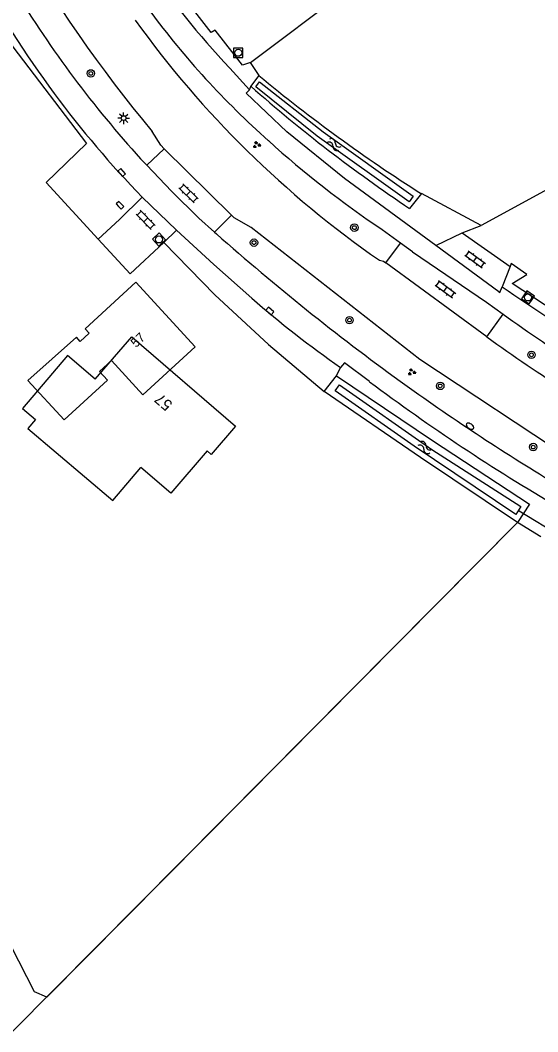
# Model space of a CAD drawing. Extents: x 134297 to 137000, y 403500 to 406000.
# Drawn here: x 136340 to 136395.5, y 404123.8 to 404232.2 of the extents above; entities that cross this region are included whole.
import ezdxf

# ---------------------------------------------------------------- set-up
doc = ezdxf.new("R2010")
doc.units = 0
for name, color, linetype in [('gg-afsc-lijn draadraster', 7, 'Continuous'), ('gg-anno-huisnummerreeks BGT', 7, 'Continuous'), ('gg-bbg-gedigitaliseerde bebouwing', 7, 'Continuous'), ('gg-bbg-hoofdgebouw', 7, 'Continuous'), ('gg-knt-bronhoudergrens', 7, 'Continuous'), ('gg-knt-verharding', 7, 'Continuous'), ('gg-kntw-bovenkant insteek waterloop', 7, 'Continuous'), ('gg-kntw-waterlijn', 7, 'Continuous'), ('gg-kwrk-duiker nz buis', 7, 'Continuous'), ('gt-anno-plantopografie huisnummer', 7, 'Continuous'), ('gt-bbg-plantopografie pand', 7, 'Continuous'), ('gt-grn-groengrens', 7, 'Continuous'), ('gt-grn-vlakafsluiter', 7, 'Continuous'), ('gt-symb-boom', 7, 'Continuous'), ('gt-symb-brandkraan', 7, 'Continuous'), ('gt-symb-groenvak', 7, 'Continuous'), ('gt-symb-klinker verharding', 7, 'Continuous'), ('gt-symb-kolk', 7, 'Continuous'), ('gt-symb-lichtmast', 7, 'Continuous'), ('gt-symb-rioolschacht', 7, 'Continuous'), ('gt-symb-watersymbool', 7, 'Continuous')]:
    doc.layers.add(name, color=color, linetype=linetype)

# ---------------------------------------------------------------- blocks, each defined once
blk = doc.blocks.new('gt0-BR')
at = {"layer": 'gt-symb-brandkraan'}
for centre, radius, start, end in [((-0.24, 0), 0.206, 107.5669, 252.4331), ((0.6, -2.66), 3, 106.892, 107.5669), ((0, -0.69), 0.938, 73.108, 106.892), ((-0.6, -2.66), 3, 72.4331, 73.108), ((0.24, 0), 0.206, 287.567, 72.4331), ((0.6, 2.66), 3, 252.4331, 253.108), ((0, 0.69), 0.938, 253.108, 286.8921), ((-0.6, 2.66), 3, 286.8921, 287.567)]:
    blk.add_arc(centre, radius, start, end, dxfattribs=at)
blk = doc.blocks.new('gt0-KL1')
at = {"layer": 'gt-symb-klinker verharding'}
for p, q in [((-1.15, 0.3), (1.15, 0.3)), ((-1, -0.3), (-1, 0.3)), ((-0.5, 0.3), (-0.5, 0.45)), ((0, -0.3), (0, 0.3)), ((0.5, 0.3), (0.5, 0.45)), ((1, -0.3), (1, 0.3)), ((-1.15, -0.3), (1.15, -0.3)), ((-0.5, -0.45), (-0.5, -0.3)), ((0.5, -0.45), (0.5, -0.3))]:
    blk.add_line(p, q, dxfattribs=at)
blk = doc.blocks.new('gt0-RS')
at = {"layer": 'gt-symb-rioolschacht'}
blk.add_lwpolyline([(-0.5, -0.5), (0.5, -0.5), (0.5, 0.5), (-0.5, 0.5)], close=True, dxfattribs=at)
blk.add_circle((0, 0), 0.375, dxfattribs=at)
blk = doc.blocks.new('gt0-BOOM')
at = {"layer": 'gt-symb-boom'}
for radius in [0.4, 0.2]:
    blk.add_circle((0, 0), radius, dxfattribs=at)
blk = doc.blocks.new('gt0-GRVAK')
at = {"layer": 'gt-symb-groenvak'}
for p, q in [((-0.11, 0.19), (-0.23, 0.24)), ((-0.18, 0.15), (0.09, 0.15)), ((-0.09, 0.21), (-0.16, 0.32)), ((-0.05, 0.21), (-0.05, 0.39)), ((0, 0.21), (0.06, 0.32)), ((0.01, 0.19), (0.13, 0.24)), ((0.26, -0.05), (0.2, 0.06)), ((0.3, -0.05), (0.3, 0.13)), ((0.35, -0.05), (0.41, 0.06)), ((-0.24, -0.23), (-0.36, -0.18)), ((-0.32, -0.26), (-0.05, -0.26)), ((-0.23, -0.21), (-0.29, -0.09)), ((-0.18, -0.2), (-0.18, -0.02)), ((-0.14, -0.21), (-0.07, -0.09)), ((-0.12, -0.23), (0, -0.18)), ((0.24, -0.07), (0.12, -0.02)), ((0.17, -0.11), (0.44, -0.11)), ((0.37, -0.07), (0.49, -0.02))]:
    blk.add_line(p, q, dxfattribs=at)
blk = doc.blocks.new('gt0-WA')
at = {"layer": 'gt-symb-watersymbool'}
for centre, start, end in [((-0.32, 0.02), 28.0725, 151.9275), ((0.43, 0.42), 208.0725, 331.9275), ((-0.32, -0.43), 28.0725, 151.9275), ((0.43, -0.03), 208.0725, 331.9275)]:
    blk.add_arc(centre, 0.425, start, end, dxfattribs=at)
blk = doc.blocks.new('gt0-KOLK')
at = {"layer": 'gt-symb-kolk'}
blk.add_lwpolyline([(0, 0), (0.38, 0), (0.38, 0.4), (-0.38, 0.4), (-0.38, 0), (0, 0)], dxfattribs=at)
blk = doc.blocks.new('gt0-LMAST')
at = {"layer": 'gt-symb-lichtmast'}
for p, q in [((-0.18, 0.17), (-0.45, 0.44)), ((-0.01, 0.25), (-0.01, 0.62)), ((0.17, 0.17), (0.44, 0.44)), ((-0.26, 0), (-0.63, 0)), ((-0.18, -0.18), (-0.45, -0.45)), ((-0.01, -0.25), (-0.01, -0.63)), ((0.44, -0.45), (0.17, -0.18)), ((0.24, 0), (0.62, 0))]:
    blk.add_line(p, q, dxfattribs=at)
blk.add_circle((-0.01, 0), 0.25, dxfattribs=at)

msp = doc.modelspace()

# ---------------------------------------------------------------- linework, layer by layer
at = {"layer": 'gg-afsc-lijn draadraster'}
msp.add_lwpolyline([(136393.29, 404178.34), (136339.17, 404123.79), (136322.77, 404159.51), (136314.88, 404154.81)], dxfattribs=at)
at = {"layer": 'gg-bbg-gedigitaliseerde bebouwing'}
msp.add_lwpolyline([(136340.84, 404193.57), (136344.73, 404189.34), (136349.37, 404193.61), (136348.52, 404194.54), (136349.78, 404195.7), (136353.15, 404192.03), (136358.75, 404197.18)], dxfattribs=at)
at = {"layer": 'gg-bbg-hoofdgebouw'}
msp.add_line((136358.75, 404197.18), (136352.39, 404204.1), dxfattribs=at)
msp.add_lwpolyline([(136352.39, 404204.1), (136346.97, 404199.08), (136347.39, 404198.62), (136346.44, 404197.75), (136346.04, 404198.21), (136340.84, 404193.57)], dxfattribs=at)
at = {"layer": 'gg-knt-bronhoudergrens'}
for points in [[(136364.7, 404227.64), (136385.02, 404242.96), (136397.01, 404251.93), (136422.89, 404264.95), (136426.7, 404255.98), (136430.43, 404247.8), (136431.22, 404241.93), (136429.87, 404236.61), (136426.38, 404230.9), (136411.85, 404222.4), (136389.39, 404210.18)], [(136393.29, 404178.34), (136342.86, 404127.51), (136341.55, 404128.06), (136336.52, 404137.85), (136327.33, 404158.36), (136324.42, 404156.97), (136322.1, 404162.19), (136316.48, 404172.64), (136308.28, 404187.53), (136302.92, 404184.22), (136298.95, 404190.84), (136305.1, 404195.07), (136301.51, 404201.61), (136285.75, 404228.6), (136285.35, 404229.26)]]:
    msp.add_lwpolyline(points, dxfattribs=at)
at = {"layer": 'gg-knt-verharding'}
for p, q in [((136364.56, 404224.71), (136362.46, 404227.04)), ((136355.43, 404218.38), (136353.57, 404216.62)), ((136362.64, 404211.28), (136355.43, 404218.38)), ((136353.4, 404216.8), (136353.57, 404216.62)), ((136350.66, 404210.82), (136353.09, 404213.2)), ((136353.09, 404213.2), (136356.76, 404209.68)), ((136362.64, 404211.28), (136360.84, 404209.44)), ((136350.66, 404210.82), (136348.37, 404208.72)), ((136355.39, 404208.34), (136356.76, 404209.68)), ((136360.84, 404209.44), (136361.03, 404209.27)), ((136380.74, 404208.28), (136378.79, 404209.72)), ((136384.53, 404208.03), (136387.36, 404209.38)), ((136387.36, 404209.38), (136392.5, 404205.78)), ((136351.79, 404204.98), (136355.39, 404208.34)), ((136379.17, 404206.15), (136380.74, 404208.28)), ((136382.04, 404207.33), (136380.74, 404208.28)), ((136391.3, 404203.06), (136384.53, 404208.03)), ((136382.04, 404207.33), (136389.98, 404201.94)), ((136389.99, 404198.23), (136379.17, 404206.15)), ((136392.5, 404205.78), (136391.63, 404203.6)), ((136389.98, 404201.94), (136391.76, 404200.66)), ((136389.99, 404198.23), (136391.76, 404200.66))]:
    msp.add_line(p, q, dxfattribs=at)
for points in [[(136384.53, 404208.03), (136374.77, 404215.2), (136368.59, 404220.2), (136364.22, 404224.33), (136364.56, 404224.71)], [(136355.43, 404218.38), (136355.08, 404218.76), (136354.15, 404220.24)], [(136353.57, 404216.62), (136356.22, 404213.83), (136359.14, 404210.96), (136360.84, 404209.44)], [(136399.14, 404185.02), (136382.83, 404195.82), (136364.76, 404209.95), (136362.95, 404210.98), (136362.64, 404211.28)], [(136364.84, 404202.37), (136360.76, 404205.98), (136356.76, 404209.68)], [(136378.5, 404206.45), (136378.93, 404206.33), (136379.17, 404206.15)], [(136391.3, 404203.06), (136391.39, 404202.99), (136391.63, 404203.6)], [(136377.42, 404193.44), (136374.74, 404195.44), (136374.34, 404194.95)]]:
    msp.add_lwpolyline(points, dxfattribs=at)
for centre, radius, start, end in [((136471.17, 404317.36), 152.07, 200.066, 219.6889), ((136456.89, 404306.95), 140.19, 203.237, 216.1199), ((136422.86, 404284.51), 83.37, 213.5802, 223.5818), ((136441.51, 404297.69), 119.62, 211.7323, 222.5531), ((136426.94, 404287.14), 90.82, 216.4374, 228.374), ((136439.87, 404295.06), 107.79, 215.7042, 235.2966), ((136431.64, 404289.49), 109.5, 216.5289, 224.1648), ((136438.44, 404298.48), 106.94, 227.8016, 236.0949), ((136535.36, 404406.62), 263.32, 228.5453, 234.0372), ((136579.7, 404479.34), 333.77, 235.7046, 239.9217), ((136439.05, 404287.52), 112.95, 228.9259, 235.0457), ((136536.3, 404402.78), 248.49, 234.4294, 239.1514), ((136498.72, 404349.7), 186.46, 234.328, 240.801), ((136521.31, 404388.31), 240.25, 234.184, 238.9049), ((136510.68, 404372.14), 222.92, 233.2885, 239.5393)]:
    msp.add_arc(centre, radius, start, end, dxfattribs=at)
at = {"layer": 'gg-kntw-bovenkant insteek waterloop'}
for p, q in [((136364.72, 404225.07), (136365.6, 404226.24)), ((136383, 404213.58), (136381.73, 404211.98)), ((136372.59, 404192.4), (136373.91, 404194.07))]:
    msp.add_line(p, q, dxfattribs=at)
for points in [[(136373.91, 404194.07), (136384.19, 404187.13), (136394.56, 404180.3), (136393.29, 404178.34)], [(136393.29, 404178.34), (136382.9, 404185.31), (136372.59, 404192.4)]]:
    msp.add_lwpolyline(points, dxfattribs=at)
for centre, radius, start, end in [((136471.33, 404353.28), 165.29, 230.229, 237.6955), ((136473.58, 404348.91), 164.88, 228.6807, 236.1456)]:
    msp.add_arc(centre, radius, start, end, dxfattribs=at)
at = {"layer": 'gg-kntw-waterlijn'}
for points in [[(136365.66, 404225.57), (136372.47, 404220.2), (136382.1, 404213.32), (136381.67, 404212.71), (136371.81, 404219.75), (136365.26, 404225.02), (136365.66, 404225.57)], [(136374.21, 404193.08), (136384.12, 404186.17), (136393.63, 404180.05), (136393.1, 404179.22), (136382.23, 404186.51), (136373.75, 404192.44), (136374.21, 404193.08)]]:
    msp.add_lwpolyline(points, dxfattribs=at)
at = {"layer": 'gg-kwrk-duiker nz buis'}
msp.add_line((136401.82, 404174.42), (136393.46, 404179.58), dxfattribs=at)
at = {"layer": 'gt-bbg-plantopografie pand'}
for points in [[(136348.06, 404193.7), (136351.96, 404198.25), (136363.09, 404188.67), (136360.48, 404185.64), (136360.04, 404186.02), (136356.14, 404181.49), (136352.94, 404184.24)], [(136348.06, 404193.7), (136345.08, 404196.23), (136340.26, 404190.55), (136341.64, 404189.37), (136340.84, 404188.43), (136349.94, 404180.71), (136352.94, 404184.24)]]:
    msp.add_lwpolyline(points, dxfattribs=at)
at = {"layer": 'gt-grn-groengrens'}
for p, q in [((136364.56, 404224.71), (136364.72, 404225.07)), ((136373.91, 404194.07), (136374.34, 404194.95)), ((136395.8, 404176.81), (136393.29, 404178.34))]:
    msp.add_line(p, q, dxfattribs=at)
for points in [[(136364.7, 404227.64), (136363.83, 404227.34), (136360.91, 404231.11), (136360.48, 404230.85), (136351.24, 404242.78), (136346.58, 404252.55)], [(136327.94, 404246.57), (136328.59, 404245.65), (136329.89, 404246.57), (136333.76, 404238.7), (136339.23, 404229.3), (136347.1, 404218.94), (136342.8, 404214.79), (136348.37, 404208.72)], [(136355.39, 404208.34), (136360.86, 404202.74), (136366.6, 404197.43), (136372.59, 404192.4)], [(136454.63, 404167.4), (136419.07, 404187.71), (136402.99, 404197.21), (136392.72, 404203.95), (136394.3, 404204.92), (136392.59, 404206.1), (136392.5, 404205.78)]]:
    msp.add_lwpolyline(points, dxfattribs=at)
at = {"layer": 'gt-grn-vlakafsluiter'}
for p, q in [((136365.6, 404226.24), (136364.7, 404227.64)), ((136389.39, 404210.18), (136383, 404213.58)), ((136387.36, 404209.38), (136389.39, 404210.18)), ((136348.37, 404208.72), (136351.79, 404204.98))]:
    msp.add_line(p, q, dxfattribs=at)

# ---------------------------------------------------------------- block references
at = {"layer": 'gt-symb-boom'}
for p in [(136347.58, 404226.46), (136375.81, 404209.94), (136365.06, 404208.33), (136375.29, 404200.03), (136394.78, 404196.31), (136385.01, 404192.98), (136394.97, 404186.43)]:
    msp.add_blockref('gt0-BOOM', p, dxfattribs=at)
at = {"layer": 'gt-symb-brandkraan', "rotation": -32.9590098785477}
msp.add_blockref('gt0-BR', (136388.21, 404188.66), dxfattribs=at)
at = {"layer": 'gt-symb-groenvak'}
for p in [(136365.34, 404218.81), (136381.94, 404194.47)]:
    msp.add_blockref('gt0-GRVAK', p, dxfattribs=at)
at = {"layer": 'gt-symb-klinker verharding'}
for p, rotation in [((136358.04, 404213.62), 135.72932696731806), ((136353.46, 404210.78), 134.02760489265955), ((136388.75, 404206.54), -36.29695894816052), ((136385.56, 404203.34), -36.45721009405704)]:
    msp.add_blockref('gt0-KL1', p, dxfattribs=dict(at, rotation=rotation))
at = {"layer": 'gt-symb-kolk'}
for p, rotation in [((136350.73, 404215.71), -49.01346679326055), ((136350.56, 404212.2), -45.9723951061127), ((136366.62, 404200.86), -40.986533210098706)]:
    msp.add_blockref('gt0-KOLK', p, dxfattribs=dict(at, rotation=rotation))
at = {"layer": 'gt-symb-lichtmast'}
msp.add_blockref('gt0-LMAST', (136351.1, 404221.67), dxfattribs=at)
at = {"layer": 'gt-symb-rioolschacht'}
msp.add_blockref('gt0-RS', (136363.37, 404228.67), dxfattribs=at)
for p, rotation in [((136354.88, 404208.67), -46.986106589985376), ((136394.41, 404202.46), -33.99203971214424)]:
    msp.add_blockref('gt0-RS', p, dxfattribs=dict(at, rotation=rotation))
at = {"layer": 'gt-symb-watersymbool', "rotation": 147.99461679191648}
for p in [(136373.69, 404218.8), (136383.41, 404186.35)]:
    msp.add_blockref('gt0-WA', p, dxfattribs=at)

# ---------------------------------------------------------------- texts
at = {"layer": 'gg-anno-huisnummerreeks BGT'}
msp.add_text('57', height=1, rotation=42.6, dxfattribs=at).set_placement((136352.41, 404197.03))
at = {"layer": 'gt-anno-plantopografie huisnummer'}
msp.add_text('57', height=1.2, rotation=139.2954, dxfattribs=at).set_placement((136356.42, 404191.11))

doc.saveas('drawing.dxf')
